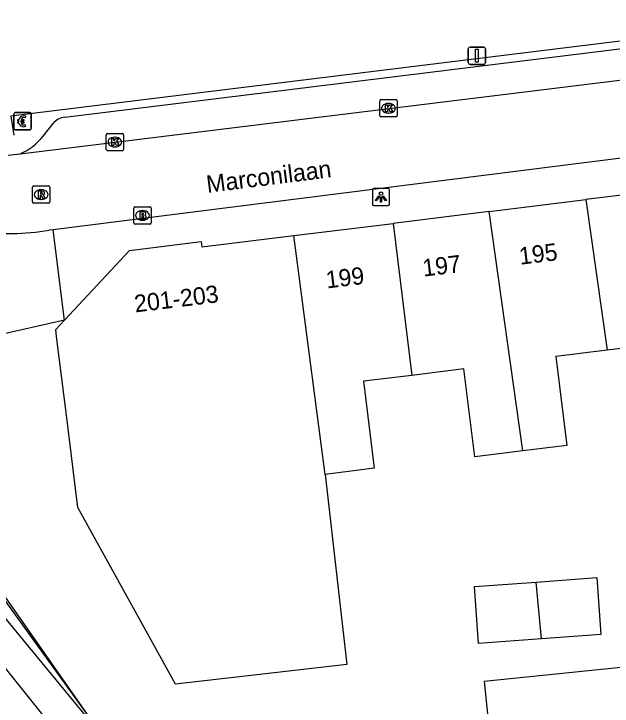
# Model space of a CAD drawing. Extents: x 159888 to 160757, y 384031 to 384746.
# Drawn here: x 159954.81 to 159989.48, y 384500.42 to 384540.54 of the extents above; entities that cross this region are included whole.
import ezdxf

# ---------------------------------------------------------------- set-up
doc = ezdxf.new("R2010")
doc.units = 0
for name, color, linetype in [('IMGEO_Betaalautomaat', 7, 'Continuous'), ('IMGEO_Brandkraan', 7, 'Continuous'), ('IMGEO_Hek', 7, 'Continuous'), ('IMGEO_Kolk', 7, 'Continuous'), ('IMGEO_Lichtpunt', 7, 'Continuous'), ('IMGEO_Openbare_ruimte_label', 7, 'Continuous'), ('IMGEO_Pand', 7, 'Continuous'), ('IMGEO_Pand_nummerreeks', 7, 'Continuous'), ('IMGEO_Rijbaan_lokaal_open', 7, 'Continuous'), ('IMGEO_Rioolput', 7, 'Continuous'), ('IMGEO_Struiken', 7, 'Continuous'), ('IMGEO_Verkeersbordpaal', 7, 'Continuous'), ('IMGEO_Voetpad_open', 7, 'Continuous')]:
    doc.layers.add(name, color=color, linetype=linetype)

msp = doc.modelspace()

# ---------------------------------------------------------------- linework, layer by layer
at = {"layer": 'IMGEO_Betaalautomaat'}
for p, q in [((159954.815, 384533.889), (159954.815, 384534.73)), ((159954.815, 384534.73), (159954.815, 384533.889)), ((159954.89, 384534.813), (159955.731, 384534.813)), ((159955.731, 384534.813), (159954.89, 384534.813)), ((159955.814, 384534.739), (159955.814, 384533.898)), ((159955.814, 384533.898), (159955.814, 384534.739)), ((159955.098, 384534.277), (159955.098, 384534.345)), ((159955.219, 384534.345), (159955.219, 384534.277)), ((159955.477, 384534.618), (159955.46, 384534.518)), ((159955.464, 384534.112), (159955.486, 384534.025)), ((159955.74, 384533.814), (159954.899, 384533.814)), ((159954.899, 384533.814), (159955.74, 384533.814))]:
    msp.add_line(p, q, dxfattribs=at)
for points in [[(159955.098, 384534.345), (159955.029, 384534.345), (159955.029, 384534.414), (159955.108, 384534.414)], [(159955.103, 384534.208), (159955.029, 384534.208), (159955.029, 384534.277), (159955.098, 384534.277)], [(159955.23, 384534.414), (159955.377, 384534.414), (159955.377, 384534.345), (159955.219, 384534.345)], [(159955.219, 384534.277), (159955.377, 384534.277), (159955.377, 384534.208), (159955.233, 384534.208)]]:
    msp.add_lwpolyline(points, dxfattribs=at)
for centre, radius, start, end in [((159954.893, 384534.736), 0.0779, 92.4484, 184.2845), ((159954.893, 384534.736), 0.0779, 92.4484, 184.2845), ((159955.737, 384534.736), 0.0779, 2.4484, 94.2845), ((159955.737, 384534.736), 0.0779, 2.4484, 94.2845), ((159955.391, 384534.338), 0.293, 73.014, 165.0139), ((159955.397, 384534.351), 0.179, 69.3236, 159.5683), ((159954.893, 384533.892), 0.0779, 182.4484, 274.2845), ((159954.893, 384533.892), 0.0779, 182.4484, 274.2845), ((159955.364, 384534.263), 0.267, 191.8096, 297.0389), ((159955.397, 384534.278), 0.179, 202.7625, 291.8693), ((159955.737, 384533.892), 0.0779, 272.4484, 4.2845), ((159955.737, 384533.892), 0.0779, 272.4484, 4.2845)]:
    msp.add_arc(centre, radius, start, end, dxfattribs=at)
at = {"layer": 'IMGEO_Brandkraan'}
for p, q in [((159961.758, 384528.431), (159961.758, 384529.283)), ((159961.833, 384529.357), (159962.685, 384529.357)), ((159962.246, 384529.137), (159962.271, 384529.137)), ((159962.759, 384529.283), (159962.759, 384528.431)), ((159962.685, 384528.357), (159961.833, 384528.357)), ((159962.269, 384528.577), (159962.244, 384528.577))]:
    msp.add_line(p, q, dxfattribs=at)
for points in [[(159961.758, 384528.431), (159961.758, 384529.283)], [(159961.833, 384529.357), (159962.685, 384529.357)], [(159962.106, 384529.057), (159962.106, 384528.657), (159962.319, 384528.657)], [(159962.337, 384529.057), (159962.106, 384529.057)], [(159962.759, 384529.283), (159962.759, 384528.431)], [(159962.285, 384528.976), (159962.231, 384528.976), (159962.231, 384528.9)], [(159962.231, 384528.9), (159962.284, 384528.9)], [(159962.293, 384528.824), (159962.231, 384528.824), (159962.231, 384528.743)], [(159962.231, 384528.743), (159962.293, 384528.743)], [(159962.685, 384528.357), (159961.833, 384528.357)]]:
    msp.add_lwpolyline(points, dxfattribs=at)
for centre, radius, start, end in [((159961.835, 384529.281), 0.0765, 91.552, 178.448), ((159961.835, 384529.281), 0.0765, 91.552, 178.448), ((159962.341, 384528.912), 0.145, 59.4692, 91.5367), ((159962.683, 384529.281), 0.0765, 1.552, 88.448), ((159962.683, 384529.281), 0.0765, 1.552, 88.448), ((159962.286, 384528.938), 0.0379, 267.8285, 90.9355), ((159962.294, 384528.783), 0.0404, 269.8759, 90.5077), ((159962.325, 384528.908), 0.251, 268.6676, 293.5347), ((159962.366, 384528.959), 0.0922, 285.5137, 58.1501), ((159962.371, 384528.767), 0.105, 301.3115, 78.989), ((159961.835, 384528.433), 0.0765, 181.552, 268.448), ((159961.835, 384528.433), 0.0765, 181.552, 268.448), ((159962.683, 384528.433), 0.0765, 271.552, 358.448), ((159962.683, 384528.433), 0.0765, 271.552, 358.448)]:
    msp.add_arc(centre, radius, start, end, dxfattribs=at)
for centre, major_axis, ratio, start_param, end_param in [((159962.245, 384528.857), (-0.387, 0.002), 0.722429, 4.712389, 7.853982), ((159962.27, 384528.857), (-0.39, 0.002), 0.717154, 1.570796, 4.712389)]:
    msp.add_ellipse(centre, major_axis=major_axis, ratio=ratio, start_param=start_param, end_param=end_param, dxfattribs=at)
at = {"layer": 'IMGEO_Hek'}
msp.add_lwpolyline([(160065.238, 384372.028), (160019.113, 384427.876), (160015.937, 384432.006), (160015.778, 384432.676), (159998.773, 384454.676), (159990.296, 384465.112), (159982.085, 384475.139), (159977.876, 384480.271), (159970.078, 384490.127), (159966.039, 384495.325), (159962.199, 384496.509), (159960.423, 384497.998), (159951.837, 384510.265), (159949.467, 384513.508), (159940.281, 384526.837), (159928.952, 384519.015)], dxfattribs=at)
at = {"layer": 'IMGEO_Kolk'}
for p, q in [((159976.02, 384534.64), (159976.02, 384535.492)), ((159976.095, 384535.566), (159976.947, 384535.566)), ((159977.021, 384535.492), (159977.021, 384534.64)), ((159976.508, 384535.346), (159976.533, 384535.346)), ((159976.531, 384534.786), (159976.506, 384534.786)), ((159976.947, 384534.566), (159976.095, 384534.566)), ((159960.166, 384532.682), (159960.166, 384533.534)), ((159960.241, 384533.608), (159961.093, 384533.608)), ((159961.167, 384533.534), (159961.167, 384532.682)), ((159960.654, 384533.388), (159960.679, 384533.388)), ((159960.677, 384532.828), (159960.652, 384532.828)), ((159961.093, 384532.608), (159960.241, 384532.608))]:
    msp.add_line(p, q, dxfattribs=at)
for points in [[(159976.02, 384534.64), (159976.02, 384535.492)], [(159976.095, 384535.566), (159976.947, 384535.566)], [(159977.021, 384535.492), (159977.021, 384534.64)], [(159976.341, 384535.266), (159976.464, 384535.266), (159976.464, 384535.115), (159976.594, 384535.266), (159976.758, 384535.266), (159976.612, 384535.115), (159976.765, 384534.866), (159976.613, 384534.866), (159976.528, 384535.03), (159976.464, 384534.963), (159976.464, 384534.866), (159976.341, 384534.866), (159976.341, 384535.266)], [(159976.947, 384534.566), (159976.095, 384534.566)], [(159960.166, 384532.682), (159960.166, 384533.534)], [(159960.241, 384533.608), (159961.093, 384533.608)], [(159961.167, 384533.534), (159961.167, 384532.682)], [(159960.487, 384533.308), (159960.61, 384533.308), (159960.61, 384533.157), (159960.74, 384533.308), (159960.904, 384533.308), (159960.758, 384533.157), (159960.911, 384532.908), (159960.759, 384532.908), (159960.674, 384533.072), (159960.61, 384533.005), (159960.61, 384532.908), (159960.487, 384532.908), (159960.487, 384533.308)], [(159961.093, 384532.608), (159960.241, 384532.608)]]:
    msp.add_lwpolyline(points, dxfattribs=at)
for centre, start, end in [((159976.097, 384535.49), 91.552, 178.448), ((159976.097, 384535.49), 91.552, 178.448), ((159976.945, 384535.49), 1.552, 88.448), ((159976.945, 384535.49), 1.552, 88.448), ((159976.097, 384534.642), 181.552, 268.448), ((159976.097, 384534.642), 181.552, 268.448), ((159976.945, 384534.642), 271.552, 358.448), ((159976.945, 384534.642), 271.552, 358.448), ((159960.243, 384533.532), 91.552, 178.448), ((159960.243, 384533.532), 91.552, 178.448), ((159961.091, 384533.532), 1.552, 88.448), ((159961.091, 384533.532), 1.552, 88.448), ((159960.243, 384532.684), 181.552, 268.448), ((159960.243, 384532.684), 181.552, 268.448), ((159961.091, 384532.684), 271.552, 358.448), ((159961.091, 384532.684), 271.552, 358.448)]:
    msp.add_arc(centre, 0.0765, start, end, dxfattribs=at)
for centre, major_axis, ratio, start_param, end_param in [((159976.507, 384535.066), (-0.387, 0.002), 0.722429, 4.712389, 7.853982), ((159976.532, 384535.066), (-0.39, 0.002), 0.717154, 1.570796, 4.712389), ((159960.653, 384533.108), (-0.387, 0.002), 0.722429, 4.712389, 7.853982), ((159960.678, 384533.108), (-0.39, 0.002), 0.717154, 1.570796, 4.712389)]:
    msp.add_ellipse(centre, major_axis=major_axis, ratio=ratio, start_param=start_param, end_param=end_param, dxfattribs=at)
at = {"layer": 'IMGEO_Lichtpunt'}
for p, q in [((159975.581, 384530.325), (159975.581, 384529.518)), ((159975.581, 384530.325), (159975.581, 384529.518)), ((159976.483, 384530.42), (159975.675, 384530.42)), ((159976.483, 384530.42), (159975.675, 384530.42)), ((159976.577, 384529.518), (159976.577, 384530.325)), ((159976.577, 384529.518), (159976.577, 384530.325)), ((159975.675, 384529.424), (159976.483, 384529.424)), ((159975.675, 384529.424), (159976.483, 384529.424))]:
    msp.add_line(p, q, dxfattribs=at)
for points in [[(159975.955, 384529.989), (159975.994, 384529.961), (159975.806, 384529.699), (159975.768, 384529.726), (159975.955, 384529.989)], [(159976.057, 384529.941), (159976.104, 384529.941), (159976.104, 384529.619), (159976.057, 384529.619), (159976.057, 384529.941)], [(159976.167, 384529.961), (159976.205, 384529.988), (159976.392, 384529.726), (159976.353, 384529.698), (159976.167, 384529.961)]]:
    msp.add_lwpolyline(points, dxfattribs=at)
msp.add_circle((159976.08, 384530.123), 0.0994, dxfattribs=at)
for centre, start, end in [((159975.675, 384530.325), 90, 180), ((159975.675, 384530.325), 90, 180), ((159976.483, 384530.325), 0, 90), ((159976.483, 384530.325), 0, 90), ((159975.675, 384529.518), 180, 270), ((159975.675, 384529.518), 180, 270), ((159976.483, 384529.518), 270, 0), ((159976.483, 384529.518), 270, 360)]:
    msp.add_arc(centre, 0.0946, start, end, dxfattribs=at)
at = {"layer": 'IMGEO_Pand'}
for points in [[(159993.526, 384530.456), (159987.948, 384529.77)], [(159982.341, 384529.081), (159987.948, 384529.77)], [(159987.948, 384529.77), (159989.187, 384521.044)], [(159982.341, 384529.081), (159976.782, 384528.398)], [(159984.303, 384515.211), (159982.341, 384529.081)], [(159971.028, 384527.691), (159976.782, 384528.398)], [(159976.782, 384528.398), (159977.872, 384519.587)], [(159957.746, 384522.792), (159961.51, 384526.828), (159965.671, 384527.34), (159965.708, 384527.037), (159971.028, 384527.691)], [(159972.84, 384513.852), (159971.028, 384527.691)], [(159972.84, 384513.852), (159974.112, 384502.834), (159964.176, 384501.687), (159958.51, 384511.936), (159957.85, 384517.285), (159957.287, 384521.846), (159957.238, 384522.247), (159957.746, 384522.792)], [(159989.187, 384521.044), (159986.211, 384520.678), (159986.845, 384515.523), (159984.303, 384515.211)], [(159995.187, 384516.582), (159993.259, 384516.342), (159992.745, 384516.278), (159992.115, 384521.404), (159989.187, 384521.044)], [(159984.303, 384515.211), (159981.511, 384514.868), (159980.886, 384519.957), (159977.872, 384519.587)], [(159977.872, 384519.587), (159975.077, 384519.243), (159975.696, 384514.203), (159972.84, 384513.852)], [(159985.07, 384507.609), (159988.589, 384507.864), (159988.829, 384504.561), (159985.39, 384504.311)], [(159985.39, 384504.311), (159981.735, 384504.046), (159981.495, 384507.35), (159985.07, 384507.609)], [(159985.39, 384504.311), (159985.07, 384507.609)], [(160006.047, 384500), (160005.605, 384504.263), (160000, 384503.69), (159982.07, 384501.855), (159982.513, 384497.53), (159986.156, 384497.904), (159986.325, 384496.284), (159997.664, 384497.43), (159998.082, 384493.443), (160000, 384493.637), (160006.638, 384494.307), (160006.047, 384500)]]:
    msp.add_lwpolyline(points, dxfattribs=at)
at = {"layer": 'IMGEO_Rijbaan_lokaal_open'}
for points in [[(159955.172, 384532.428), (159995.091, 384537.337), (160000, 384537.965), (160003.846, 384538.379)], [(160006.181, 384534.24), (160005.545, 384534.15), (160000, 384533.435), (159998.881, 384533.291), (159957.092, 384528.025)], [(159954.479, 384532.343), (159955.172, 384532.428)], [(159957.092, 384528.025), (159956.853, 384527.995)]]:
    msp.add_lwpolyline(points, dxfattribs=at)
msp.add_arc((159954.464, 384543.017), 15.211, 262.9552, 279.0375, dxfattribs=at)
at = {"layer": 'IMGEO_Rioolput'}
for p, q in [((159955.887, 384529.638), (159955.887, 384530.49)), ((159955.962, 384530.564), (159956.814, 384530.564)), ((159956.375, 384530.344), (159956.4, 384530.344)), ((159956.888, 384530.49), (159956.888, 384529.638)), ((159956.814, 384529.564), (159955.962, 384529.564)), ((159956.398, 384529.784), (159956.373, 384529.784))]:
    msp.add_line(p, q, dxfattribs=at)
for points in [[(159955.887, 384529.638), (159955.887, 384530.49)], [(159955.962, 384530.564), (159956.814, 384530.564)], [(159956.476, 384530.262), (159956.224, 384530.264), (159956.224, 384529.864)], [(159956.888, 384530.49), (159956.888, 384529.638)], [(159956.224, 384529.864), (159956.348, 384529.864), (159956.348, 384530.026), (159956.359, 384530.026)], [(159956.402, 384530.183), (159956.348, 384530.183), (159956.348, 384530.102)], [(159956.348, 384530.102), (159956.4, 384530.102)], [(159956.406, 384529.997), (159956.477, 384529.864), (159956.617, 384529.864), (159956.552, 384529.99)], [(159956.814, 384529.564), (159955.962, 384529.564)]]:
    msp.add_lwpolyline(points, dxfattribs=at)
for centre, radius, start, end in [((159955.964, 384530.488), 0.0765, 91.552, 178.448), ((159955.964, 384530.488), 0.0765, 91.552, 178.448), ((159956.475, 384530.152), 0.109, 350.3612, 89.416), ((159956.812, 384530.488), 0.0765, 1.552, 88.448), ((159956.812, 384530.488), 0.0765, 1.552, 88.448), ((159956.358, 384529.973), 0.0533, 26.0293, 88.6989), ((159956.384, 384530.291), 0.19, 274.7715, 282.9687), ((159956.408, 384530.087), 0.0964, 77.0061, 93.1865), ((159956.422, 384530.144), 0.0378, 276.6634, 79.6772), ((159956.473, 384530.152), 0.112, 277.5842, 350.9817), ((159956.457, 384529.937), 0.108, 29.5134, 73.7905), ((159955.964, 384529.64), 0.0765, 181.552, 268.448), ((159955.964, 384529.64), 0.0765, 181.552, 268.448), ((159956.812, 384529.64), 0.0765, 271.552, 358.448), ((159956.812, 384529.64), 0.0765, 271.552, 358.448)]:
    msp.add_arc(centre, radius, start, end, dxfattribs=at)
for centre, major_axis, ratio, start_param, end_param in [((159956.374, 384530.064), (-0.387, 0.002), 0.722429, 4.712389, 7.853982), ((159956.399, 384530.064), (-0.39, 0.002), 0.717154, 1.570796, 4.712389)]:
    msp.add_ellipse(centre, major_axis=major_axis, ratio=ratio, start_param=start_param, end_param=end_param, dxfattribs=at)
at = {"layer": 'IMGEO_Struiken'}
for points in [[(159960.035, 384498.56), (159945.112, 384516.689), (159942.251, 384519.231), (159938.612, 384522.024), (159943.244, 384516.426), (159958.634, 384497.212), (159968.849, 384484.162), (159988.685, 384459.311), (160014.515, 384427.415), (160032.134, 384405.962), (160063.25, 384368.855)], [(159945.955, 384518.046), (159960.035, 384498.56)]]:
    msp.add_lwpolyline(points, dxfattribs=at)
at = {"layer": 'IMGEO_Verkeersbordpaal'}
for p, q in [((159981.142, 384537.712), (159981.142, 384538.512)), ((159981.142, 384538.512), (159981.142, 384537.712)), ((159981.242, 384538.612), (159982.032, 384538.612)), ((159982.032, 384538.612), (159981.242, 384538.612)), ((159982.132, 384538.512), (159982.132, 384537.712)), ((159982.132, 384537.712), (159982.132, 384538.512)), ((159982.032, 384537.612), (159981.242, 384537.612)), ((159981.242, 384537.612), (159982.032, 384537.612))]:
    msp.add_line(p, q, dxfattribs=at)
msp.add_lwpolyline([(159981.562, 384538.487), (159981.712, 384538.487), (159981.712, 384537.737), (159981.562, 384537.737), (159981.562, 384538.487)], dxfattribs=at)
for centre, start, end in [((159981.242, 384538.512), 90, 180), ((159981.242, 384538.512), 90, 180), ((159982.032, 384538.512), 0, 90), ((159982.032, 384538.512), 360, 90), ((159981.242, 384537.712), 180, 270), ((159981.242, 384537.712), 180, 270), ((159982.032, 384537.712), 270, 0), ((159982.032, 384537.712), 270, 0)]:
    msp.add_arc(centre, 0.1, start, end, dxfattribs=at)
at = {"layer": 'IMGEO_Voetpad_open'}
for points in [[(159990.51, 384546.175), (159996.159, 384544.238), (159999.453, 384542.468), (160001.842, 384540.938), (160001.435, 384540.309), (159995.91, 384539.694), (159954.636, 384534.609), (159954.8, 384533.502)], [(159957.757, 384534.553), (159995.866, 384539.238), (160000.892, 384539.812)], [(159956.502, 384533.456), (159957.085, 384534.179)], [(159957.746, 384522.792), (159957.092, 384528.025)], [(159957.746, 384522.792), (159949.872, 384521.004)]]:
    msp.add_lwpolyline(points, dxfattribs=at)
for centre, radius, start, end in [((159957.887, 384533.529), 1.032, 97.225, 140.971), ((159954.036, 384535.272), 3.062, 291.7697, 323.6335)]:
    msp.add_arc(centre, radius, start, end, dxfattribs=at)

# ---------------------------------------------------------------- texts
at = {"layer": 'IMGEO_Openbare_ruimte_label'}
msp.add_text('Marconilaan', height=1, rotation=7.2387, dxfattribs=at).set_placement((159966.025, 384530.16))
at = {"layer": 'IMGEO_Pand_nummerreeks'}
for s, p in [('195', (159984.144, 384525.997)), ('197', (159978.547, 384525.309)), ('199', (159972.949, 384524.622)), ('201-203', (159961.849, 384523.234))]:
    msp.add_text(s, height=1, rotation=7.0073, dxfattribs=at).set_placement(p)

doc.saveas('drawing.dxf')
